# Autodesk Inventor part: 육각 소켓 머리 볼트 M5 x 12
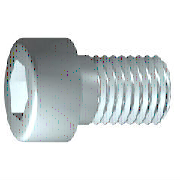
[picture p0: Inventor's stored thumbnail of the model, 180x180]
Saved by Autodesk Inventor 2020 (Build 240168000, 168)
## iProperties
Created: 2012-02
Part Number: 육각 소켓 머리 볼트 M5 x 12
Material: 강철, 연강
Description: 6각 소켓 머리 캡 나사
Document SubType Name: Modeling
Standard: ISO 4762
Designer: mdu-01
Standard Revision: Fourth edition 2004-03-01
Standards Organization: ISO
Language: ko-KR
Size Designation: M5 x 12
Categories: <MemberInstance><Categories><Category DisplayName="조임쇠" InternalName="e4da775c-781d-43d5-af7c-5136215cf5a6" Mnemonic="FSTN"><Category DisplayName="볼트" InternalN
Density: 7.86 g/cm^3
Mass: 3.72825 g
Surface Area: 4.62573 cm^2
Volume: 0.474332 cm^3
Appearance: 강철
Author: mdu-01
IsCustomPart: 1
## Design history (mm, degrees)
sketch "스케치1"
  geometry: L1 (-1.167, 0)-(12, 0); L2 (12, 0)-(12, 2.5); L3 (12, 2.5)-(2, 2.5); L4 (2, 2.5)-(1.509, 2.5); L5 (1.509, 2.5)-(0, 2.5); L6 (0, 2.5)-(0, 4.25); L7 (0, 4.25)-(-5, 4.25); L8 (-5, 4.25)-(-5, 2.309); L9 (-5, 2.309)-(-2.5, 2.309); L10 (-2.5, 2.309)-(-1.167, 0); L11 (-8.4, 0)-(15.4, 0) reference; L12 (0, -0.85)-(0, 5.1) reference; L13 (2, 2.5)-(0, 2.5)
  constraints: 22 end point, 6 parallel, 2 collinear, 2 perpendicular, 1 horizontal, 1 point on line
  dimensions: "d1" = 10 distance from line of L3.end L2 (= GEL); "d2" = 0.49086 distance of L4.end L3.end (computed from GAL); "d3" = 5 distance between parallel lines of L8 L6 (= KOH); "d4" = 2.5 distance of L8.end L9.end (= INTI); "d5" = 60 deg angle of L10 L1; "d6" = 5 diameter of L3 L1 (= GD); "d7" = 5 diameter of L5 L1 (= BDM); "d8" = 4.6188 diameter of L9 L1 (= 1.1547 x SW); "d9" = 8.5 diameter of L7 L1 (= KOD); "d26" = 12 distance between parallel lines of L12 L2 (= NLG)
revolve "본체" sketch "스케치1" stored, may be unused: angle "d10" = 90 deg
sketch "스케치2"
  geometry: L1 (0, -5.95)-(0, 5.95) reference; L2 (-5.95, 0)-(5.95, 0) reference; L3 (2.309, 0)-(1.155, -2); L4 (1.155, -2)-(-1.155, -2); L5 (-1.155, -2)-(-2.309, 0); L6 (-2.309, 0)-(-1.155, 2); L7 (-1.155, 2)-(1.155, 2); L8 (1.155, 2)-(2.309, 0); 2 further points
  constraints: 12 end point, 1 coincident, 1 horizontal alignment, 1 point on line, 12 other
extrude "슬롯" join sketch "스케치2" stored distance "d11" = 10; taper "d12" = 0 deg
workplane "Work Plane1"
fillet "Fillet2" dims "d30" = 0.1 (= R)
body "Solid1"
fillet "모깎기1" dims "d17" = 0.5 (= RR)
feature "스레드" dims "d13" = 10 (= GEL), "d14" = 0
chamfer "모따기1" distance "d15" = 0.49076 (= -0.5 x SPD + 0.5 x GD); stored, may be unused: second distance "d16" = 0.49076 (= GUL), angle "d27" = 45 deg
other parameters: "GD" = 5 [user parameter; used in 2 equation terms], "NLG" = 12 [user parameter; used in 1 equation term], "GEL" = 10 [user parameter; used in 2 equation terms], "KOD" = 8.5 [user parameter; used in 1 equation term], "KOH" = 5 [user parameter; used in 1 equation term], "INTI" = 2.5 [user parameter; used in 1 equation term], "GAL" = 0.49076 (= 0.61345 x PTC) [user parameter; used in 1 equation term], "GUL" = 0.49076 (= 0.61345 x PTC) [user parameter; used in 1 equation term], "BDM" = 5 (= NND) [user parameter; used in 1 equation term], "SW" = 4 [user parameter; used in 2 equation terms], "RR" = 0.5 [user parameter; used in 1 equation term], "SPD" = 4.01848 (= NND - 1.2269 x PTC) [user parameter; used in 1 equation term], "d19" = 0, "d28" = 0, "d29" = 0, "R" = 0.1 [user parameter; used in 1 equation term], "TOA" = 30 deg [user parameter], "GD1" = 4.01848 (= THREADDIA - 1.2269 x PTC) [user parameter], "THREADDIA" = 5 [user parameter; used in 1 equation term], "FAWI" = 45 deg [user parameter], "TPU" = 12.5 (computed from PTC) [user parameter], "PTC" = 0.8 [user parameter; used in 5 equation terms], "NND" = 5 [user parameter; used in 2 equation terms], "E0" = 4.62 (= 1.155 x SW) [user parameter]
